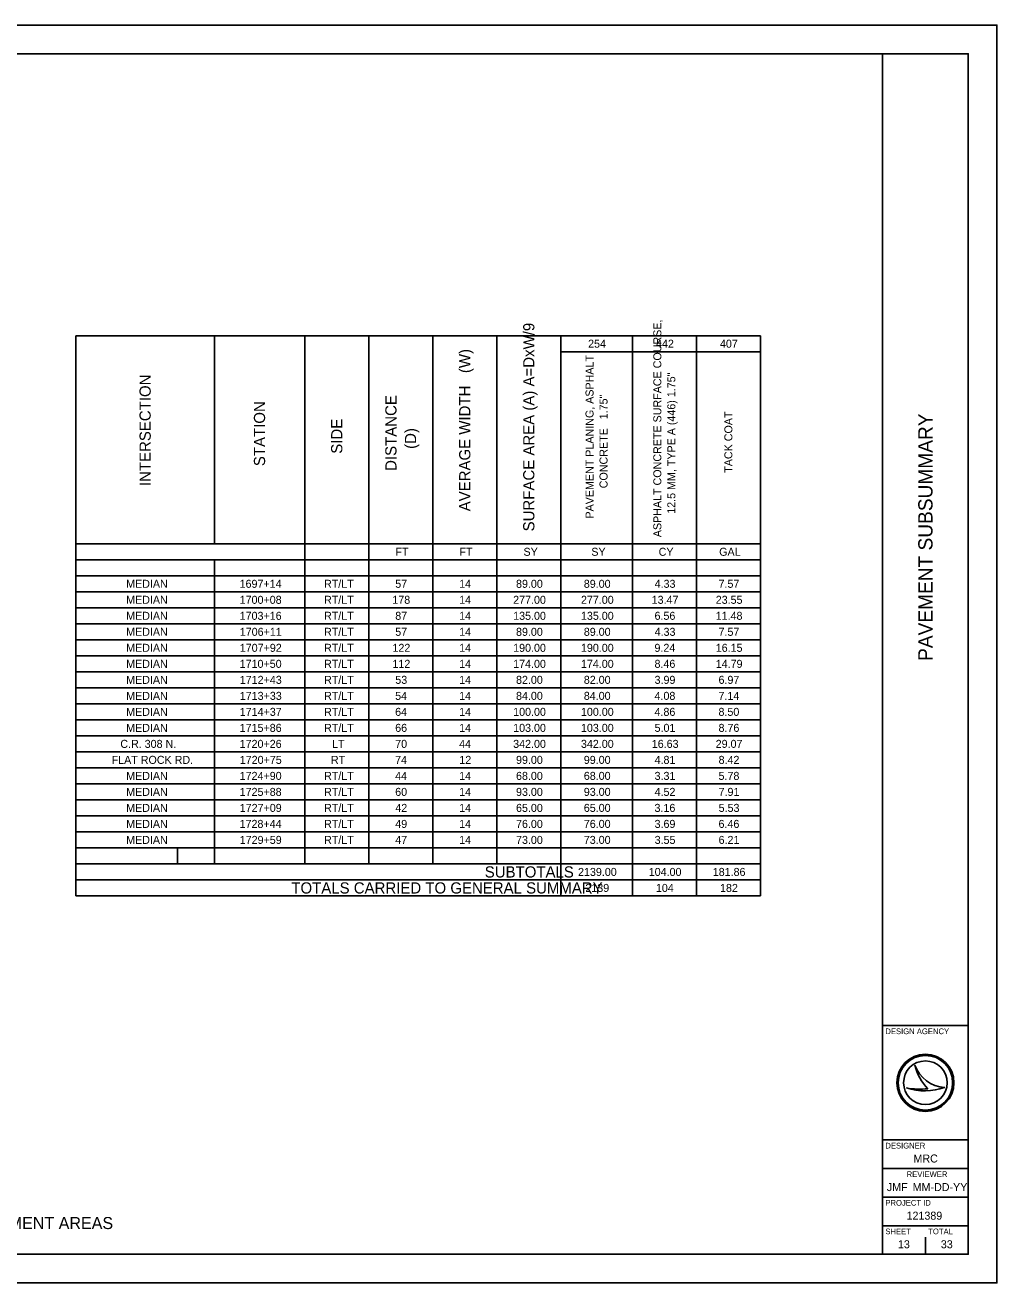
# Model space of a CAD drawing. Extents: x 0 to 34, y 0 to 22.
# Drawn here: x 17 to 34, y 0 to 22 of the extents above; entities that cross this region are included whole.
import ezdxf

# ---------------------------------------------------------------- set-up
doc = ezdxf.new("R2010")
doc.units = 0
for name, color, linetype in [('SH_Border', 7, 'Continuous'), ('SH_Cut_Line', 7, 'Continuous'), ('SH_Data', 7, 'Continuous'), ('SH_Text', 7, 'Continuous')]:
    doc.layers.add(name, color=color, linetype=linetype)

msp = doc.modelspace()

# ---------------------------------------------------------------- linework, layer by layer
at = {"layer": 'SH_Border'}
for p, q in [((32, 0.5), (32, 21.5)), ((32, 4.5), (33.5, 4.5)), ((32, 2.5), (33.5, 2.5)), ((32, 2), (33.5, 2)), ((32, 1.5), (33.5, 1.5)), ((32, 1), (33.5, 1))]:
    msp.add_line(p, q, dxfattribs=at)
msp.add_lwpolyline([(1.5, 21.5), (33.5, 21.5), (33.5, 0.5), (1.5, 0.5)], close=True, dxfattribs=at)
at = {"layer": 'SH_Cut_Line'}
msp.add_lwpolyline([(0, 0), (34, 0), (34, 22), (0, 22)], close=True, dxfattribs=at)
at = {"layer": 'SH_Data'}
for p, q in [((17.889, 16.568), (29.863, 16.568)), ((17.889, 16.568), (17.889, 6.768)), ((20.31, 16.568), (20.31, 12.928)), ((21.891, 16.568), (21.891, 7.328)), ((23.011, 16.568), (23.011, 7.328)), ((24.131, 16.568), (24.131, 7.328)), ((25.251, 16.568), (25.251, 7.328)), ((26.371, 16.568), (26.371, 16.288)), ((27.623, 16.568), (27.623, 6.768)), ((28.743, 16.568), (28.743, 6.768)), ((29.863, 16.568), (29.863, 6.768)), ((26.371, 16.288), (29.863, 16.288)), ((26.371, 16.288), (26.371, 6.768)), ((17.889, 12.928), (29.863, 12.928)), ((17.889, 12.648), (29.863, 12.648)), ((20.31, 12.648), (20.31, 7.328)), ((17.889, 12.368), (29.863, 12.368)), ((17.889, 12.088), (29.863, 12.088)), ((17.889, 11.808), (29.863, 11.808)), ((17.889, 11.528), (29.863, 11.528)), ((17.889, 11.248), (29.863, 11.248)), ((17.889, 10.968), (29.863, 10.968)), ((17.889, 10.688), (29.863, 10.688)), ((17.889, 10.408), (29.863, 10.408)), ((17.889, 10.128), (29.863, 10.128)), ((17.889, 9.848), (29.863, 9.848)), ((17.889, 9.568), (29.863, 9.568)), ((17.889, 9.288), (29.863, 9.288)), ((17.889, 9.008), (29.863, 9.008)), ((17.889, 8.728), (29.863, 8.728)), ((17.889, 8.448), (29.863, 8.448)), ((17.889, 8.168), (29.863, 8.168)), ((17.889, 7.888), (29.863, 7.888)), ((17.889, 7.608), (29.863, 7.608)), ((19.667, 7.608), (19.667, 7.328)), ((17.889, 7.328), (29.863, 7.328)), ((17.889, 7.048), (29.863, 7.048)), ((17.889, 6.768), (29.863, 6.768)), ((32.567, 3.81), (32.567, 3.81)), ((32.417, 3.41), (32.417, 3.41)), ((32.75, 3.5), (32.75, 3.5)), ((33.087, 3.419), (33.087, 3.419)), ((32.375, 0.675), (32.375, 0.675)), ((32.75, 0.5), (32.75, 0.8))]:
    msp.add_line(p, q, dxfattribs=at)
for radius in [0.5, 0.477, 0.477, 0.382]:
    msp.add_circle((32.75, 3.5), radius, dxfattribs=at)
for centre, radius, start, end in [((33.116, 3.998), 0.58, 198.9257, 198.9319), ((33.347, 3.97), 0.796, 191.6379, 191.6421), ((33.116, 3.998), 0.58, 198.9319, 267.1657), ((33.347, 3.97), 0.796, 191.6421, 226.0947), ((32.739, 4.37), 1.013, 251.4576, 290.0832), ((32.648, 4.654), 1.266, 259.4964, 259.4995), ((32.739, 4.37), 1.013, 251.4527, 251.4576), ((32.648, 4.654), 1.266, 259.4995, 276.6672)]:
    msp.add_arc(centre, radius, start, end, dxfattribs=at)

# ---------------------------------------------------------------- texts
msp.add_text('PAVEMENT SUBSUMMARY', height=0.25, rotation=90, dxfattribs=at).set_placement((32.875, 10.879))
for s, height, p in [('DESIGN AGENCY', 0.1, (32.05, 4.35)), ('DESIGNER', 0.1, (32.05, 2.35)), ('MRC', 0.14, (32.541, 2.105)), ('REVIEWER', 0.1, (32.422, 1.85)), ('JMF', 0.14, (32.075, 1.605)), ('MM-DD-YY', 0.14, (32.527, 1.605)), ('PROJECT ID', 0.1, (32.05, 1.35)), ('121389', 0.14, (32.42, 1.105)), ('SHEET', 0.1, (32.05, 0.85)), ('TOTAL', 0.1, (32.8, 0.85)), ('13', 0.14, (32.27, 0.605)), ('33', 0.14, (33.02, 0.605))]:
    msp.add_text(s, height=height, dxfattribs=at).set_placement(p)
at = {"layer": 'SH_Text'}
for s, height, p in [('SURFACE AREA (A) A=DxW/9', 0.196, (25.909, 13.145)), ('ASPHALT CONCRETE SURFACE COURSE, ', 0.14, (28.13, 13.043)), ('AVERAGE WIDTH   (W)', 0.196, (24.789, 13.496)), ('PAVEMENT PLANING, ASPHALT ', 0.14, (26.944, 13.369)), ('INTERSECTION', 0.196, (19.197, 13.937)), ('12.5 MM, TYPE A (446) 1.75"', 0.14, (28.375, 13.453)), ('STATION', 0.196, (21.198, 14.286)), ('DISTANCE                                                                                                        ', 0.196, (23.497, 14.203)), ('CONCRETE   1.75"', 0.14, (27.189, 13.899)), ('TACK COAT', 0.14, (29.373, 14.17)), ('SIDE', 0.196, (22.549, 14.503)), ('(D)', 0.196, (23.84, 14.588))]:
    msp.add_text(s, height=height, rotation=90, dxfattribs=at).set_placement(p)
for s, height, p in [('254', 0.14, (26.849, 16.358)), ('442', 0.14, (28.037, 16.358)), ('407', 0.14, (29.156, 16.358)), ('FT', 0.14, (23.478, 12.718)), ('FT', 0.14, (24.598, 12.718)), ('SY', 0.14, (25.719, 12.718)), ('SY', 0.14, (26.905, 12.718)), ('CY', 0.14, (28.083, 12.718)), ('GAL', 0.14, (29.142, 12.718)), ('MEDIAN', 0.14, (18.767, 12.158)), ('1697+14', 0.14, (20.752, 12.158)), ('RT/LT', 0.14, (22.229, 12.158)), ('57', 0.14, (23.475, 12.158)), ('14', 0.14, (24.593, 12.158)), ('89.00', 0.14, (25.588, 12.158)), ('89.00', 0.14, (26.774, 12.158)), ('4.33', 0.14, (28.013, 12.158)), ('7.57', 0.14, (29.131, 12.158)), ('MEDIAN', 0.14, (18.767, 11.878)), ('1700+08', 0.14, (20.753, 11.878)), ('RT/LT', 0.14, (22.229, 11.878)), ('178', 0.14, (23.424, 11.878)), ('14', 0.14, (24.593, 11.878)), ('277.00', 0.14, (25.538, 11.878)), ('277.00', 0.14, (26.724, 11.878)), ('13.47', 0.14, (27.961, 11.878)), ('23.55', 0.14, (29.082, 11.878)), ('MEDIAN', 0.14, (18.767, 11.598)), ('1703+16', 0.14, (20.753, 11.598)), ('RT/LT', 0.14, (22.229, 11.598)), ('87', 0.14, (23.475, 11.598)), ('14', 0.14, (24.593, 11.598)), ('135.00', 0.14, (25.538, 11.598)), ('135.00', 0.14, (26.724, 11.598)), ('6.56', 0.14, (28.011, 11.598)), ('11.48', 0.14, (29.081, 11.598)), ('MEDIAN', 0.14, (18.767, 11.318)), ('1706+11', 0.14, (20.755, 11.318)), ('RT/LT', 0.14, (22.229, 11.318)), ('57', 0.14, (23.475, 11.318)), ('14', 0.14, (24.593, 11.318)), ('89.00', 0.14, (25.588, 11.318)), ('89.00', 0.14, (26.774, 11.318)), ('4.33', 0.14, (28.013, 11.318)), ('7.57', 0.14, (29.131, 11.318)), ('MEDIAN', 0.14, (18.767, 11.038)), ('1707+92', 0.14, (20.755, 11.038)), ('RT/LT', 0.14, (22.229, 11.038)), ('122', 0.14, (23.426, 11.038)), ('14', 0.14, (24.593, 11.038)), ('190.00', 0.14, (25.538, 11.038)), ('190.00', 0.14, (26.724, 11.038)), ('9.24', 0.14, (28.01, 11.038)), ('16.15', 0.14, (29.082, 11.038)), ('MEDIAN', 0.14, (18.767, 10.758)), ('1710+50', 0.14, (20.753, 10.758)), ('RT/LT', 0.14, (22.229, 10.758)), ('112', 0.14, (23.426, 10.758)), ('14', 0.14, (24.593, 10.758)), ('174.00', 0.14, (25.538, 10.758)), ('174.00', 0.14, (26.724, 10.758)), ('8.46', 0.14, (28.011, 10.758)), ('14.79', 0.14, (29.082, 10.758)), ('MEDIAN', 0.14, (18.767, 10.478)), ('1712+43', 0.14, (20.755, 10.478)), ('RT/LT', 0.14, (22.229, 10.478)), ('53', 0.14, (23.476, 10.478)), ('14', 0.14, (24.593, 10.478)), ('82.00', 0.14, (25.588, 10.478)), ('82.00', 0.14, (26.774, 10.478)), ('3.99', 0.14, (28.012, 10.478)), ('6.97', 0.14, (29.131, 10.478)), ('1713+33', 0.14, (20.755, 10.198)), ('RT/LT', 0.14, (22.229, 10.198)), ('84.00', 0.14, (25.588, 10.198)), ('84.00', 0.14, (26.774, 10.198)), ('4.08', 0.14, (28.011, 10.198)), ('MEDIAN', 0.14, (18.767, 10.198)), ('54', 0.14, (23.473, 10.198)), ('14', 0.14, (24.593, 10.198)), ('7.14', 0.14, (29.13, 10.198)), ('MEDIAN', 0.14, (18.767, 9.918)), ('1714+37', 0.14, (20.754, 9.918)), ('RT/LT', 0.14, (22.229, 9.918)), ('64', 0.14, (23.473, 9.918)), ('14', 0.14, (24.593, 9.918)), ('100.00', 0.14, (25.538, 9.918)), ('100.00', 0.14, (26.724, 9.918)), ('4.86', 0.14, (28.011, 9.918)), ('8.50', 0.14, (29.13, 9.918)), ('MEDIAN', 0.14, (18.767, 9.638)), ('1715+86', 0.14, (20.753, 9.638)), ('RT/LT', 0.14, (22.229, 9.638)), ('66', 0.14, (23.474, 9.638)), ('14', 0.14, (24.593, 9.638)), ('103.00', 0.14, (25.538, 9.638)), ('103.00', 0.14, (26.724, 9.638)), ('5.01', 0.14, (28.012, 9.638)), ('8.76', 0.14, (29.131, 9.638)), ('C.R. 308 N.', 0.14, (18.665, 9.358)), ('1720+26', 0.14, (20.753, 9.358)), ('LT', 0.14, (22.369, 9.358)), ('70', 0.14, (23.474, 9.358)), ('44', 0.14, (24.593, 9.358)), ('342.00', 0.14, (25.538, 9.358)), ('342.00', 0.14, (26.724, 9.358)), ('16.63', 0.14, (27.963, 9.358)), ('29.07', 0.14, (29.081, 9.358)), ('FLAT ROCK RD.', 0.14, (18.513, 9.078)), ('1720+75', 0.14, (20.755, 9.078)), ('RT', 0.14, (22.35, 9.078)), ('74', 0.14, (23.473, 9.078)), ('12', 0.14, (24.596, 9.078)), ('99.00', 0.14, (25.588, 9.078)), ('99.00', 0.14, (26.774, 9.078)), ('4.81', 0.14, (28.012, 9.078)), ('8.42', 0.14, (29.132, 9.078)), ('MEDIAN', 0.14, (18.767, 8.798)), ('1724+90', 0.14, (20.753, 8.798)), ('RT/LT', 0.14, (22.229, 8.798)), ('44', 0.14, (23.473, 8.798)), ('14', 0.14, (24.593, 8.798)), ('68.00', 0.14, (25.588, 8.798)), ('68.00', 0.14, (26.774, 8.798)), ('3.31', 0.14, (28.012, 8.798)), ('5.78', 0.14, (29.131, 8.798)), ('MEDIAN', 0.14, (18.767, 8.518)), ('1725+88', 0.14, (20.753, 8.518)), ('RT/LT', 0.14, (22.229, 8.518)), ('60', 0.14, (23.474, 8.518)), ('14', 0.14, (24.593, 8.518)), ('93.00', 0.14, (25.588, 8.518)), ('93.00', 0.14, (26.774, 8.518)), ('4.52', 0.14, (28.012, 8.518)), ('7.91', 0.14, (29.132, 8.518)), ('MEDIAN', 0.14, (18.767, 8.238)), ('1727+09', 0.14, (20.754, 8.238)), ('RT/LT', 0.14, (22.229, 8.238)), ('42', 0.14, (23.476, 8.238)), ('14', 0.14, (24.593, 8.238)), ('65.00', 0.14, (25.588, 8.238)), ('65.00', 0.14, (26.774, 8.238)), ('3.16', 0.14, (28.011, 8.238)), ('5.53', 0.14, (29.133, 8.238)), ('MEDIAN', 0.14, (18.767, 7.958)), ('1728+44', 0.14, (20.752, 7.958)), ('RT/LT', 0.14, (22.229, 7.958)), ('49', 0.14, (23.475, 7.958)), ('14', 0.14, (24.593, 7.958)), ('76.00', 0.14, (25.588, 7.958)), ('76.00', 0.14, (26.774, 7.958)), ('3.69', 0.14, (28.012, 7.958)), ('6.46', 0.14, (29.131, 7.958)), ('MEDIAN', 0.14, (18.767, 7.678)), ('1729+59', 0.14, (20.754, 7.678)), ('RT/LT', 0.14, (22.229, 7.678)), ('47', 0.14, (23.475, 7.678)), ('14', 0.14, (24.593, 7.678)), ('73.00', 0.14, (25.588, 7.678)), ('73.00', 0.14, (26.774, 7.678)), ('3.55', 0.14, (28.013, 7.678)), ('6.21', 0.14, (29.132, 7.678)), ('SUBTOTALS', 0.196, (25.041, 7.09)), ('2139.00', 0.14, (26.673, 7.118)), ('104.00', 0.14, (27.91, 7.118)), ('181.86', 0.14, (29.03, 7.118)), ('TOTALS CARRIED TO GENERAL SUMMARY', 0.196, (21.657, 6.81)), ('2139', 0.14, (26.801, 6.838)), ('104', 0.14, (28.035, 6.838)), ('182', 0.14, (29.157, 6.838)), ('EXTRA PAVEMENT AREAS', 0.21, (14.95, 0.941))]:
    msp.add_text(s, height=height, dxfattribs=at).set_placement(p)

doc.saveas('drawing.dxf')
